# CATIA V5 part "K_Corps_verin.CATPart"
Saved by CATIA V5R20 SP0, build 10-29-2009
Part number: Corps_verin
Publications: "Face"
Bounding box of the stored display mesh (mm): x -11 to 23.5, y -15.42 to 11.046, z -205.19 to 7.233
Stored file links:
  G:\Khaled_CFAO_2011\SIL\SIL_GR2\zthiebault\Khaled\CAD_ThinkMOTION\K_Corps_verin.CATPart
  F:\Projet Thinkmotion\Catia\FINAL\HabillageFinal.CATProduct
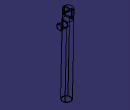
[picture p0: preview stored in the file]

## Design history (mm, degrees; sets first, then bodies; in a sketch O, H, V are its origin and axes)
External parameters (linked from other documents)
  External.diamcorpsext = 22 mm
  External.diamverin = 20 mm
  External.longcorpsverin = 205 mm
  External.hauteurexcroissance = 30 mm
  External.rayonaxepivot = 2 mm
Set1
  Plane1 "Plan_base_corpsverin2": linked copy from another document
  Line1 "Droite_base_corpsverin": linked copy from another document
  Plane2 "Plan_base_corpsverin": linked copy from another document
  Point1 "Point_base_corpsverin": linked copy from another document
  Line2 "Droite_base_corpsverin2": linked copy from another document
  DatumSurface1: linked copy from another document
  DatumSurface2: linked copy from another document
  DatumCurve1: linked copy from another document
Set2
  Plane3: type 2Lines, Element1 Line1, Element2 Line2
Body1 (main body)
  Sketch1 on Plane1, origin (0, 0, 0), H (0.9578, -0.2876, 0), V (0.0059, 0.0198, 0.9998)
    line L1 (-0.0434, 6.9999) -> (10.9564, 7.0681)
    line L2 (10.9564, 7.0681) -> (12.2717, -204.9278)
    line L3 (12.2717, -204.9278) -> (1.2719, -204.9961)
    line L4 (1.2719, -204.9961) -> (-0.0434, 6.9999)
    reference projected line E1 (0, 0) -> (1.2719, -204.9961) from Line1
    reference intersected line E2 through (1.2719, -204.9961) direction (1, 0.0062) from Plane2
    reference projected point E3 (0, 0) from Point1
    distance E3 L1 = 7
    length L3 = 11 {= External.diamcorpsext /2}
    coincidence: L4 E1, L3 E2
    parallelism: L4 L2, L3 L1
    perpendicularity: L1 L4
  Shaft1: profile Sketch1, axis Line1, angle 360
  Sketch2 on face of Shaft1 from Sketch1.L3, origin (0, -4.4226, -204.9523), H (1, 0, 0), V (0, -0.9998, 0.0216)
    point P1 (0, 0)
  Hole1: placed by Sketch2, at (0, -4.4226, -204.9523) direction (0, 0.0216, 0.9998), diameter 20 {= External.diamverin}, depth 187 {= External.longcorpsverin -External.hauteurexcroissance /2-3mm}
  Sketch3 on Plane3, origin (0, 0, 0), H (1, 0, 0), V (0, 0.0216, 0.9998)
    line L1 (-1.5, 10) -> (1.5, 10)
    line L2 (1.5, 10) -> (1.5, -12.5112)
    line L3 (1.5, -12.5112) -> (-1.5, -12.5112)
    line L4 (-1.5, -12.5112) -> (-1.5, 10)
    reference intersected line E1 through (-1.5, 0) direction (0, 1) from face of DatumSurface1
    reference intersected line E2 through (1.5, 0) direction (0, 1) from face of DatumSurface2
    reference intersected line E3 (-11, 7) -> (11, 7) from face of Shaft1 from Sketch1.L1
    reference projected line E4 (1.5, -14.5112) -> (-1.5, -14.5112) from edge of DatumCurve1
    distance L1 E3 = 3
    distance E4 L3 = 2
    horizontal: L1 H, L3 H
    vertical: L2 V, L4 V
    coincidence: L4 E1, L2 E2
  Pocket1: profile Sketch3, direction (0, 0.9998, -0.0216), through (limit type 6), opposite side through (limit type 6)
  Sketch4 on face of Pocket1 from Sketch3.L4, origin (-1.5, -9.5221, -1.4324), H (0, 1, 0), V (0, 0, 1)
    point P1 (9.5221, 1.4324)
    reference projected point E1 (9.5221, 1.4324) from Line2
    coincidence: P1 E1
  Hole2: placed by Sketch4, at (-1.5, 0, 0) direction (-1, 0, 0), diameter 4 {= External.rayonaxepivot *2}, through (limit type 6)
  Sketch5 on face of Pocket1 from Sketch3.L2, origin (1.5, -8.1202, 0.844), H (0, 1, 0), V (0, 0, -1)
    point P1 (8.1202, 0.844)
    reference projected point E1 (8.1202, 0.844) from Line2
    coincidence: P1 E1
  Hole3: placed by Sketch5, at (1.5, 0, 0) direction (1, 0, 0), diameter 4 {= External.rayonaxepivot *2}, through (limit type 6)
  Sketch6 on face of Pocket1 from Sketch3.L2, origin (1.5, 0, 0), H (0, -1, 0), V (0, 0, 1)
    circle A1 centre (0.5609, -25.9939) radius 8
    point P1 (0.5609, -25.9939)
    reference projected line E1 (0, 0) -> (4.4226, -204.9523) from Line1
    reference intersected line E2 (-9.4962, -18.2091) -> (10.2729, -17.7825) from face of Hole1
    radius A1 = 8
    distance P1 E2 = 8 {= Sketch6.radius(A1)}
    coincidence: P1 E1
  Pad1: profile Sketch6, direction (1, 0, 0), length 22, opposite side length -6
  Fillet1: radius 2, on edge [end face of Pad1 | face of Pad1 from Sketch6.A1]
